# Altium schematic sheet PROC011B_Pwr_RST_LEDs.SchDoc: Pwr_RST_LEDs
size 431 x 279 mm; Date: Not shown in title block; ApprovedBy: Not shown in title block; CheckedBy: Not shown in title block; Author: Not shown in title block; CompanyName: Not shown in title block; Engineer: Not shown in title block; Organization: Not shown in title block; Address1: Not shown in title block; Address2: Not shown in title block; Address3: Not shown in title block; Address4: Not shown in title block; DocumentNumber: 1; Revision: Use project parameter SCH_Rev; SheetNumber: 7; SheetTotal: 17; PageSetup: Record=PageOptions¦CenterHorizontal=True¦CenterVertical=True¦PrintScale=1.00¦XCorrection=1.00¦YCorrection=1.00¦PrintKind=0¦BorderSize=5000000¦LeftOffset=0¦BottomOffset=0¦Orientation=2¦PaperLength=1000¦PaperWidth=1000¦Scale=100¦PaperSource=15¦PrintQuality=600¦MediaType=1¦DitherType=10¦PaperKind=Letter¦PrintScaleMode=1
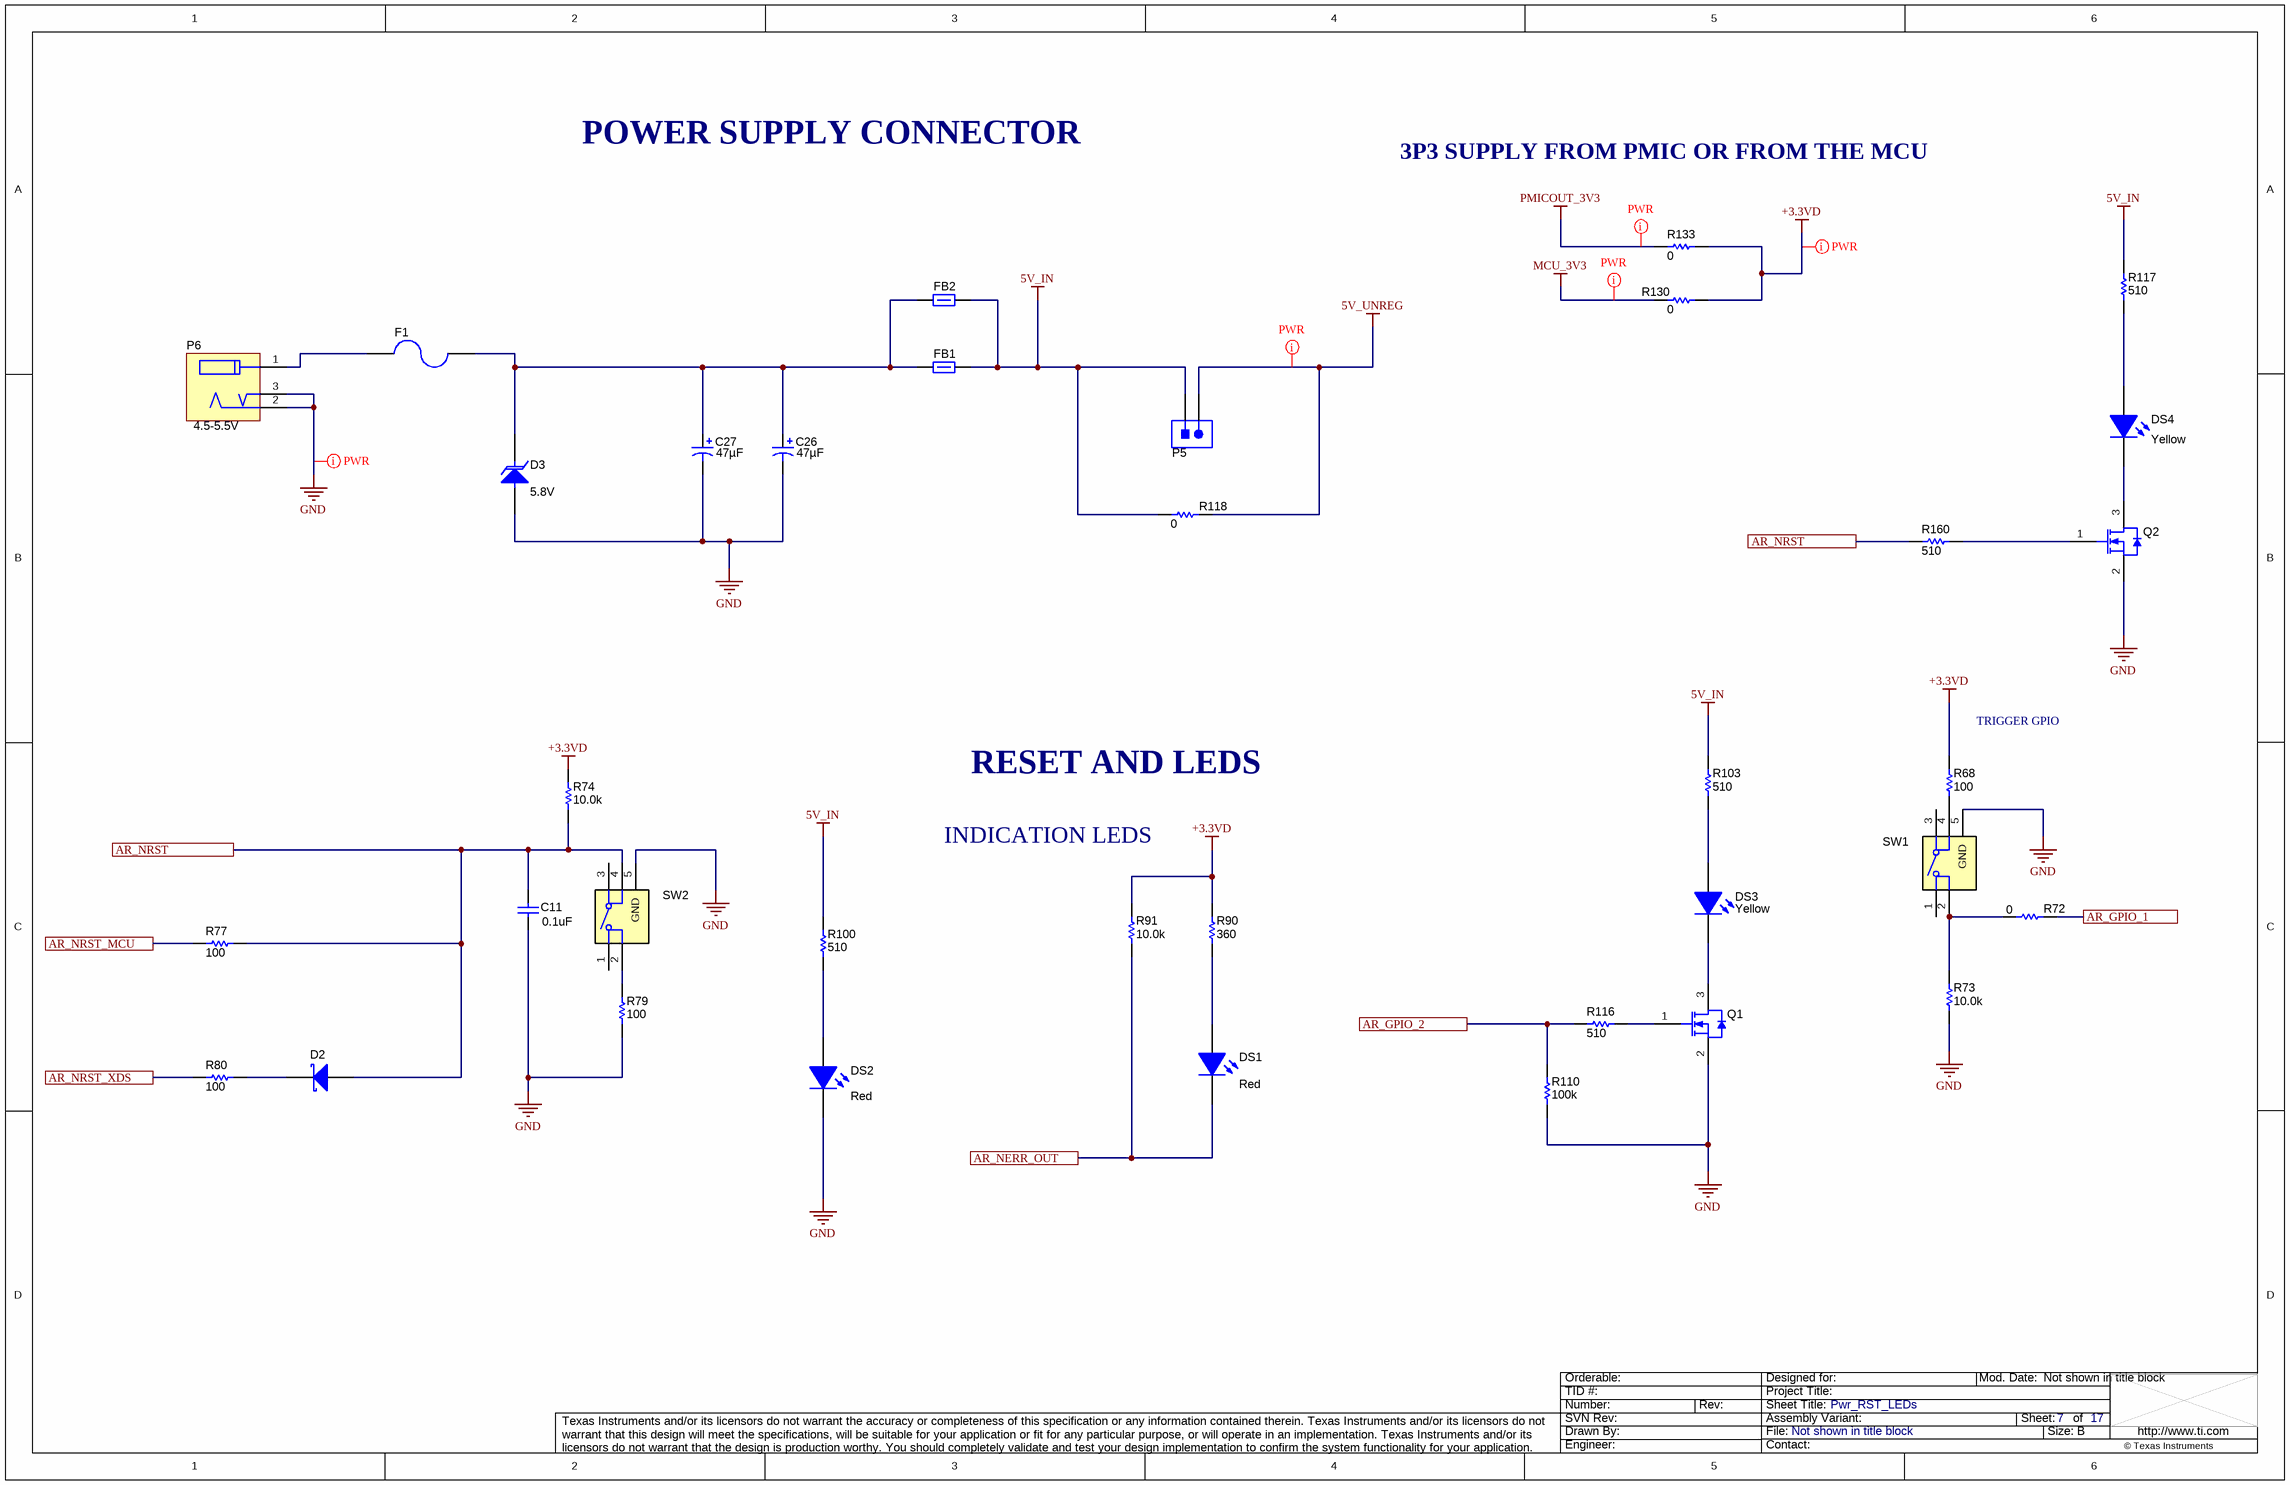
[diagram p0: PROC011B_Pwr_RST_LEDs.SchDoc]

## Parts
C11  ValueDisplayed: 0.1uF  [0402L]  (hidden comment: GCM155R71C104KA55D)
C26  ValueDisplayed: 47µF  [3528-21]  (hidden comment: T491B476K010AT)
C27  ValueDisplayed: 47µF  [3528-21]  (hidden comment: T491B476K010AT)
D2  SMS3923-040LF  [SOD-882]  (value not drawn)
D3  value 5.8V  [SMB]  (hidden comment: SZP6SMB6.8AT3G)
DS1  value Red  [TLMx1000_Red]  (hidden comment: TLMS1000-GS08)
DS2  value Red  [TLMx1000_Red]  (hidden comment: TLMS1000-GS08)
DS3  value Yellow  [TLMx1000_Yellow]  (hidden comment: TLMY1000-GS08)
DS4  value Yellow  [TLMx1000_Yellow]  (hidden comment: TLMY1000-GS08)
F1  0440005.WR  [1206]  (value not drawn)
FB1  BLM21PG300SH1D  [0805_HV]  (value not drawn)
FB2  BLM21PG300SH1D  [0805_HV]  (value not drawn)
P5  TSW-102-07-G-S  [TSW-102-07-X-S]  (value not drawn)
P6  Voltage_V: 4.5-5.5V  [CUI_PJ-002AH]  (hidden comment: PJ-002AH)
Q1  BSS123  [SOT-23]  (value not drawn)
Q2  BSS123  [SOT-23]  (value not drawn)
R68  ValueDisplayed: 100  [0402L]  (hidden comment: ERJ-2GEJ101X)
R72  ValueDisplayed: 0  [0201_Silk]  (hidden comment: CRCW02010000Z0ED)
R73  ValueDisplayed: 10.0k  [0402L]  (hidden comment: CRCW040210K0FKED)
R74  ValueDisplayed: 10.0k  [0402L]  (hidden comment: CRCW040210K0FKED)
R77  ValueDisplayed: 100  [0402L]  (hidden comment: ERJ-2GEJ101X)
R79  ValueDisplayed: 100  [0402L]  (hidden comment: ERJ-2GEJ101X)
R80  ValueDisplayed: 100  [0402L]  (hidden comment: ERJ-2GEJ101X)
R90  ValueDisplayed: 360  [0402L]  (hidden comment: ERJ-2GEJ361X)
R91  ValueDisplayed: 10.0k  [0402L]  (hidden comment: CRCW040210K0FKED)
R100  ValueDisplayed: 510  [0402L]  (hidden comment: ERJ-2GEJ511X)
R103  ValueDisplayed: 510  [0402L]  (hidden comment: ERJ-2GEJ511X)
R110  ValueDisplayed: 100k  [0402L]  (hidden comment: CRCW0402100KFKED)
R116  ValueDisplayed: 510  [0402L]  (hidden comment: ERJ-2GEJ511X)
R117  ValueDisplayed: 510  [0402L]  (hidden comment: ERJ-2GEJ511X)
R118  ValueDisplayed: 0  [2010]  (hidden comment: CRCW20100000Z0EF)
R130  ValueDisplayed: 0  [0603]  (hidden comment: MCT06030Z0000ZP500)
R133  ValueDisplayed: 0  [0603]  (hidden comment: MCT06030Z0000ZP500)
R160  ValueDisplayed: 510  [0402L]  (hidden comment: ERJ-2GEJ511X)
SW1  KMR243GLFG  [SW_KMR243GLFG]  (value not drawn)
SW2  KMR243GLFG  [SW_KMR243GLFG]  (value not drawn)

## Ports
AR_GPIO_1, AR_GPIO_2, AR_NERR_OUT, AR_NRST, AR_NRST_MCU, AR_NRST_XDS

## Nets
5V_IN: FB1.2 FB2.2 P5.1 R100.2 R103.2 R117.2 R118.1
5V_UNREG: P5.2 R118.2
+3.3VD: R68.2 R74.2 R90.2 R91.2 R130.2 R133.2
GND: C11.1 C26.2(-) C27.2(-) D3.2(A) DS2.2(K) P6.2 P6.3 Q1.2(S) Q2.2(S) R73.1 R79.1 R110.1 SW1.5(GND) SW2.5(GND)
MCU_3V3: R130.1
PMICOUT_3V3: R133.1
AR_GPIO_1: R72.2 ; port AR_GPIO_1
AR_GPIO_2: R110.2 R116.1 ; port AR_GPIO_2
AR_NERR_OUT: DS1.2(K) R91.1 ; port AR_NERR_OUT
AR_NRST: C11.2 D2.2(A) R74.1 R77.2 R160.1 SW2.4 ; port AR_NRST
AR_NRST_MCU: R77.1 ; port AR_NRST_MCU
AR_NRST_XDS: R80.1 ; port AR_NRST_XDS
NetC26_1: C26.1(+) C27.1(+) D3.1(K) F1.1 FB1.1 FB2.1
NetD2_1: D2.1(K) R80.2
NetDS1_1: DS1.1(A) R90.1
NetDS2_1: DS2.1(A) R100.1
NetDS3_1: DS3.1(A) R103.1
NetDS3_2: DS3.2(K) Q1.3(D)
NetDS4_1: DS4.1(A) R117.1
NetDS4_2: DS4.2(K) Q2.3(D)
NetF1_2: F1.2 P6.1
NetQ1_1: Q1.1(G) R116.2
NetQ2_1: Q2.1(G) R160.2
NetR68_1: R68.1 SW1.4
NetR72_1: R72.1 R73.2 SW1.2
NetR79_2: R79.2 SW2.2

Not connected (* = marked no-connect by the designer): SW1 1 3; SW2 1 3

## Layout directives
net class PWR: 5V_UNREG, +3.3VD, GND, MCU_3V3, PMICOUT_3V3

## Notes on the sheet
- POWER SUPPLY CONNECTOR
- 3P3 SUPPLY FROM PMIC OR FROM THE MCU
- (near R68) TRIGGER GPIO
- RESET AND LEDS
- INDICATION LEDS

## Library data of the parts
C11 = CMP-0006351-2: CAP, CERM, 0.1 uF, 16 V, +/- 10%, X7R, 0402; Manufacturer: MuRata; TaMin_C: -55°C; Polarized: N; SizeAreaWB_mm2: 3; Value1: Unknown; U/M: EA; Value: 0.1uF; TaMax_C: 125°C; SizeZ_mm: 0.6; SizeX_mm: 1; SizeY_mm: 0.5; Cap_Case: 0402; Value2: 16V; Cap_F: 100nF; AEC Category: Q200
C26 C27 = CMP-0078216-1: CAP, TA, 47 µF, 10 V, +/- 10%, SMD; Manufacturer: Kemet; TaMin_C: -55°C; Polarized: Y; SizeAreaWB_mm2: 17.1; Value: 47uF; TaMax_C: 125°C; SizeZ_mm: 2.1; SizeX_mm: 3.5; SizeY_mm: 2.8; Value2: 10V; SizeArea_mm2: 9.8; CompType: Capacitor; AEC Qualified: N; AEC Category: Q200
D2 = CMP-0078187-1: Diode, Schottky,  V, 0.01 A, SOD-882; Manufacturer: Skyworks Solutions; SizeAreaWB_mm2: 3.2; SizeArea_mm2: 0.6; AEC Qualified: N; TJmax_C: 150°C; AEC Category: Q101; SizeZ_mm: 0.5; Io_A: 10mA; Vf_V: 3.4dV; Value2: 0.34V; Value1: 0.01A; SizeX_mm: 1
D3 = CMP-0078243-1: Diode, TVS, Uni, 5.8 V, 10.5 Vc, AEC-Q101, SMB; Manufacturer: Littelfuse; Power_W: 550mW; SizeAreaWB_mm2: 44.156; Value1: 0.55W; RJA_CperW: 226; SizeZ_mm: 2.6; SizeX_mm: 5.6; SizeY_mm: 3.81; SizeArea_mm2: 21.336; AEC Qualified: Y; AEC Category: Q101
DS1 DS2 = CMP-0078197-1: LED, Red, SMD; Manufacturer: Vishay-Semiconductor; Tjmax_C: 120°C; SizeAreaWB_mm2: 4.68; Vr_V: 6V; Power_TotalModule: 40mW; Angle: 160; SizeArea_mm2: 1.28; Ir_A: 10µA; SizeZ_mm: 0.65; Io_A: 2mA; Vf_V: 1.8V; SizeY_mm: 0.8; U/M: EA; Value1: .04W; SizeX_mm: 1.6; Type: AlInGaP
DS3 DS4 = CMP-0078196-1: LED, Yellow, SMD; Manufacturer: Vishay-Semiconductor; Tjmax_C: 120°C; SizeAreaWB_mm2: 4.68; Vr_V: 6V; Power_TotalModule: 40mW; Angle: 160; SizeArea_mm2: 1.28; Ir_A: 10µA; SizeZ_mm: 0.65; Io_A: 2mA; Vf_V: 1.8V; SizeY_mm: 0.8; U/M: EA; Value1: .04W; SizeX_mm: 1.6; Type: AlInGaP
F1 = CMP-0003458-1: Fuse, 5 A, 32VAC/VDC, SMD; Manufacturer: Littelfuse; Irating_A: 5A; SizeAreaWB_mm2: 10.92; Interrupt_AC: 50A; VAC_V: 32V; SizeZ_mm: 1.35; SizeX_mm: 3.2; SizeY_mm: 1.6; SizeArea_mm2: 5.12; Rtyp_Ohm: 0.012; MeltingTyp: 4.761
FB1 = CMP-0003364-1: Ferrite Bead, 30 ohm @ 100 MHz, 4 A, 0805; Manufacturer: MuRata; ZTyp@100MHz_Ohm: 30; SizeAreaWB_mm2: 6.75; DCR_ohm: 0.014; Value1: 0.014 ohm; Value: 30 ohm; Imax_A: 4A; SizeZ_mm: 1.45; SizeX_mm: 2; SizeY_mm: 1.25; SizeArea_mm2: 2.5
FB2 = CMP-0003364-1: Ferrite Bead, 30 ohm @ 100 MHz, 4 A, 0805; Manufacturer: MuRata; ZTyp@100MHz_Ohm: 30; SizeAreaWB_mm2: 6.75; DCR_ohm: 0.014; Value1: 0.014 ohm; Value: 30 ohm; Imax_A: 4A; SizeZ_mm: 1.45; SizeX_mm: 2; SizeY_mm: 1.25; SizeArea_mm2: 2.5; INSTALLATION: DNP
P5 = CMP-0075405-1: Header, 100mil, 2x1, Gold, TH; Manufacturer: Samtec; Pitch_mm: 2.54; Cert_VDE: N; Gender: Male; Cert_CSA: Y; Voltage_V: 550V; Green_REACh: Passed; Current_A: 6.3A; CT: False; Green_Lifecycle: Active; Row_Count: 1; CNHeader: True
P6 = CMP-0078270-1: DC POWER JACK, R/A, TH; Manufacturer: CUI Inc.; Gender: Female; Cert_UL: Y; Current_A: 5A; Green_REACh: Incomplete; Green_Lifecycle: Not Set
Q1 Q2 = CMP-0000947-2: MOSFET, N-CH, 100 V, 0.17 A, SOT-23; Alternate Manufacturer: None; Manufacturer: Fairchild Semiconductor; SizeZ_mm: 1.1; ChType: N; Value2: 1.8 nC; Value1: 1; VdsMax_V: 100V; SizeX_mm: 2.5; SizeY_mm: 3; Vgs_V: 20V; Value: 100V; Rdson45_ohm: 10; SizeArea_mm2: 7.5; AEC Category: Q101; IdsMax_A: 1.7dA; SizeAreaWB_mm2: 14; U/M: EA; QgTyp_nC: 1.8
R68 R77 R79 R80 = CMP-0026993-2: RES, 100, 5%, 0.1 W, AEC-Q200 Grade 0, 0402; Manufacturer: Panasonic; Power_W: 100mW; TempCo: 200 ppm/C; Value_Code: 100R; U/M: EA; Value: 100; EIA_Code: E24; SizeX_mm: 1; SizeY_mm: 0.5; SizeZ_mm: 0.6; Value2: 0.1W; AEC Qualified: Y; AEC Grade: 0; AEC Category: Q200
R72 = CMP-0027008-3: RES, 0, 5%, 0.05 W, 0201; Manufacturer: Vishay-Dale; Power_W: 50mW; TempCo: ppm/C; Value_Code: 0000; U/M: EA; Value: 0; EIA_Code: E24; SizeX_mm: 0.6; SizeY_mm: 0.3; SizeZ_mm: 0.26; Value2: 0.05W; SizeArea_mm2: 0.18; AEC Qualified: N; AEC Category: Q200
R73 R74 R91 = CMP-0025958-2: RES, 10.0 k, 1%, 0.063 W, 0402; Manufacturer: Vishay-Dale; Power_W: 63mW; TempCo: 100 ppm/C; Value_Code: 10k0; U/M: EA; Value: 10.0k; EIA_Code: E96; Res_ohm: 10k; SizeX_mm: 1; SizeY_mm: 0.5; SizeZ_mm: 0.6; Value2: 0.063W; VDC_V: 50V; AEC Category: Q200
R90 = CMP-0078194-1: RES, 360, 5%, 0.1 W, AEC-Q200 Grade 0, 0402; Manufacturer: Panasonic; Value_Code: 360R; SizeArea_mm2: 0.5; AEC Qualified: Y; AEC Category: Q200; Value: 360; SizeZ_mm: 0.6; EIA_Code: E24; TempCo: 200 ppm/C; AEC Grade: 0; Power_W: 100mW; VDC_V: 50V; Value2: 0.1W; U/M: EA; SizeX_mm: 1
R100 R103 R116 R117 R160 = CMP-0078212-1: RES, 510, 5%, 0.1 W, AEC-Q200 Grade 0, 0402; Manufacturer: Panasonic; Value_Code: 510R; SizeArea_mm2: 0.5; AEC Qualified: Y; AEC Category: Q200; Value: 510; SizeZ_mm: 0.6; EIA_Code: E24; TempCo: 200 ppm/C; AEC Grade: 0; Power_W: 100mW; VDC_V: 50V; Value2: 0.1W; U/M: EA; SizeX_mm: 1
R110 = CMP-0025950-2: RES, 100 k, 1%, 0.063 W, 0402; Manufacturer: Vishay-Dale; Power_W: 63mW; TempCo: 100 ppm/C; U/M: EA; Value: 100k; EIA_Code: E96; SizeX_mm: 1; SizeY_mm: 0.5; SizeZ_mm: 0.6; Value2: 0.063W; VDC_V: 50V; AEC Category: Q200
R118 = CMP-0016044-2: RES, 0, 5%, 0.75 W, AEC-Q200 Grade 0, 2010; Manufacturer: Vishay-Dale; Power_W: 750mW; TempCo: ppm/C; Value_Code: 0000; U/M: EA; Value: 0; EIA_Code: E24; SizeX_mm: 5; SizeY_mm: 2.5; SizeZ_mm: 1.66; Value2: 0.75W; SizeArea_mm2: 12.5; AEC Qualified: Y; AEC Category: Q200
R130 = CMP-0025884-3: RES, 0, 5%, 0.125 W, 0603; Manufacturer: Vishay/Beyschlag; Power_W: 125mW; TempCo: ppm/C; Value_Code: 0000; U/M: EA; Value: 0; EIA_Code: E24; SizeX_mm: 1.6; SizeY_mm: 0.8; SizeZ_mm: 1; Value2: 0.125W; SizeArea_mm2: 1.28; CompType: Resistor; AEC Qualified: N; AEC Category: Q200; INSTALATION: DNP
R133 = CMP-0025884-3: RES, 0, 5%, 0.125 W, 0603; Manufacturer: Vishay/Beyschlag; Power_W: 125mW; TempCo: ppm/C; Value_Code: 0000; U/M: EA; Value: 0; EIA_Code: E24; SizeX_mm: 1.6; SizeY_mm: 0.8; SizeZ_mm: 1; Value2: 0.125W; SizeArea_mm2: 1.28; AEC Qualified: N; AEC Category: Q200
SW1 SW2 = CMP-0002325-1: Switch, SPST-NO, Off-Mom, 0.01 A, 32 VDC, SMD; Manufacturer: C&K Components; CurrentRating_mA: 10A; PositionCount: 1; SizeX_mm: 4.6; SizeY_mm: 2.8; SizeZ_mm: 1.9; SizeArea_mm2: 12.88; VDC_V: 32V; SizeAreaWB_mm2: 21.28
